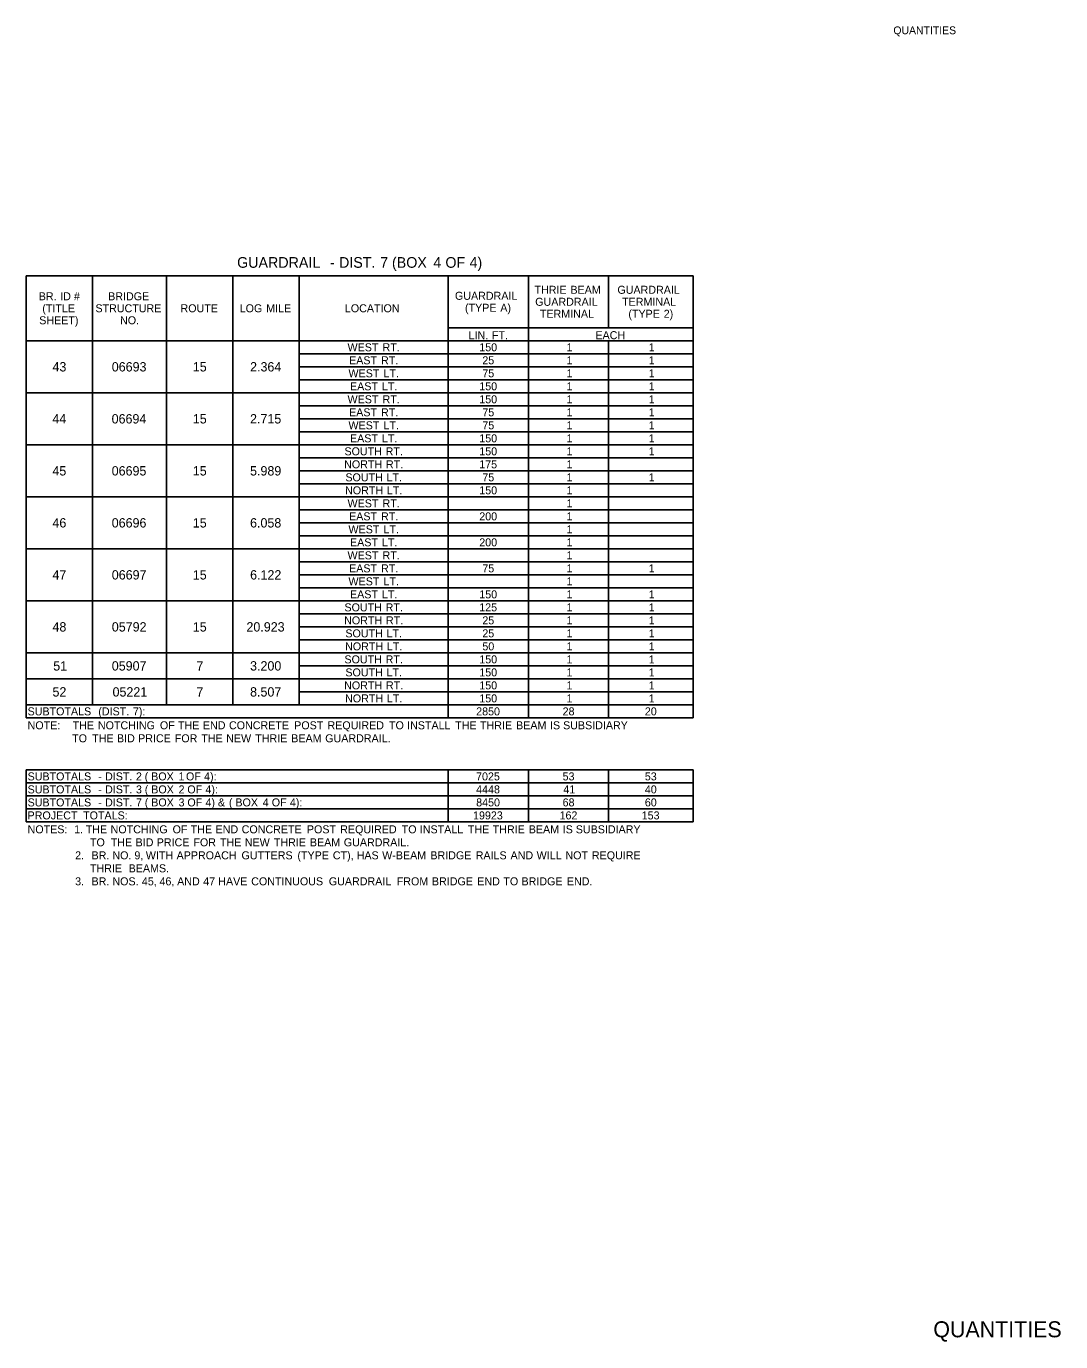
# Model space of a CAD drawing. Extents: x 544250 to 1930787, y -1948365 to 596640.
# Drawn here: x 550713 to 551489, y -1947044 to -1946058 of the extents above; entities that cross this region are included whole.
import ezdxf

# ---------------------------------------------------------------- set-up
doc = ezdxf.new("R2010")
doc.units = 0
for name, color, linetype in [('Default', 7, 'Continuous'), ('R_Border', 7, 'Continuous'), ('R_Border Prem', 7, 'Continuous')]:
    doc.layers.add(name, color=color, linetype=linetype)

msp = doc.modelspace()

# ---------------------------------------------------------------- linework, layer by layer
at = {"layer": 'Default'}
for p, q in [((550712.7, -1946245.01), (551212.87, -1946245.01)), ((550712.7, -1946245.01), (551212.87, -1946245.01)), ((550712.7, -1946576.51), (550712.7, -1946245.01)), ((550712.7, -1946576.51), (550712.7, -1946245.01)), ((550762.42, -1946566.76), (550762.42, -1946245.01)), ((550818, -1946566.76), (550818, -1946245.01)), ((550867.72, -1946566.76), (550867.72, -1946245.01)), ((550917.45, -1946566.76), (550917.45, -1946245.01)), ((551029.09, -1946576.51), (551029.09, -1946245.01)), ((551089.54, -1946576.51), (551089.54, -1946245.01)), ((551149.5, -1946284.01), (551149.5, -1946245.01)), ((551212.87, -1946576.51), (551212.87, -1946245.01)), ((551212.87, -1946293.76), (551212.87, -1946245.01)), ((551029.09, -1946284.01), (551212.87, -1946284.01)), ((551089.54, -1946293.76), (551089.54, -1946284.01)), ((550712.7, -1946293.76), (551212.87, -1946293.76)), ((551149.5, -1946576.51), (551149.5, -1946293.76)), ((550917.45, -1946303.51), (551212.87, -1946303.51)), ((550917.45, -1946313.26), (551212.87, -1946313.26)), ((550917.45, -1946323.01), (551212.87, -1946323.01)), ((550712.7, -1946332.76), (551212.87, -1946332.76)), ((550917.45, -1946342.51), (551212.87, -1946342.51)), ((550917.45, -1946352.26), (551212.87, -1946352.26)), ((550917.45, -1946362.01), (551212.87, -1946362.01)), ((550712.7, -1946371.76), (551212.87, -1946371.76)), ((550917.45, -1946381.51), (551212.87, -1946381.51)), ((550917.45, -1946391.26), (551212.87, -1946391.26)), ((550917.45, -1946401.01), (551212.87, -1946401.01)), ((550712.7, -1946410.76), (551212.87, -1946410.76)), ((550917.45, -1946420.51), (551212.87, -1946420.51)), ((550917.45, -1946430.26), (551212.87, -1946430.26)), ((550917.45, -1946440.01), (551212.87, -1946440.01)), ((550712.7, -1946449.76), (551212.87, -1946449.76)), ((550917.45, -1946459.51), (551212.87, -1946459.51)), ((550917.45, -1946469.26), (551212.87, -1946469.26)), ((550917.45, -1946479.01), (551212.87, -1946479.01)), ((550712.7, -1946488.76), (551212.87, -1946488.76)), ((551212.87, -1946576.51), (551212.87, -1946488.76)), ((550917.45, -1946498.51), (551212.87, -1946498.51)), ((550917.45, -1946508.26), (551212.87, -1946508.26)), ((550917.45, -1946518.01), (551212.87, -1946518.01)), ((550712.7, -1946527.76), (551212.87, -1946527.76)), ((550917.45, -1946537.51), (551212.87, -1946537.51)), ((550712.7, -1946547.26), (550917.45, -1946547.26)), ((550762.42, -1946547.26), (550917.45, -1946547.26)), ((550917.45, -1946547.26), (551212.87, -1946547.26)), ((550917.45, -1946547.26), (551212.87, -1946547.26)), ((550917.45, -1946557.01), (551212.87, -1946557.01)), ((550712.7, -1946566.76), (551212.87, -1946566.76)), ((550762.42, -1946566.76), (550917.45, -1946566.76)), ((550917.45, -1946566.76), (551212.87, -1946566.76)), ((551089.54, -1946576.51), (551089.54, -1946566.76)), ((551149.5, -1946576.51), (551149.5, -1946566.76)), ((550712.7, -1946576.51), (551212.87, -1946576.51)), ((550712.7, -1946615.51), (551212.87, -1946615.51)), ((550712.7, -1946654.51), (550712.7, -1946615.51)), ((550712.7, -1946654.51), (550712.7, -1946615.51)), ((551029.09, -1946654.51), (551029.09, -1946615.51)), ((551089.54, -1946654.51), (551089.54, -1946615.51)), ((551149.5, -1946654.51), (551149.5, -1946615.51)), ((551212.87, -1946654.51), (551212.87, -1946615.51)), ((551212.87, -1946654.51), (551212.87, -1946615.51)), ((550712.7, -1946625.26), (551212.87, -1946625.26)), ((550712.7, -1946635.01), (551212.87, -1946635.01)), ((550712.7, -1946644.76), (551212.87, -1946644.76)), ((550712.7, -1946654.51), (551212.87, -1946654.51))]:
    msp.add_line(p, q, dxfattribs=at)

# ---------------------------------------------------------------- texts
for s, height, p in [('GUARDRAIL', 8, (550870.85, -1946239.01)), (' DIST.', 8, (550944.33, -1946239.01)), (' 7', 8, (550975.23, -1946239.01)), (' (BOX', 8, (550984.06, -1946239.01)), (' 4', 8, (551015.09, -1946239.01)), (' OF', 8, (551024.15, -1946239.01)), (' 4)', 8, (551042.26, -1946239.01)), (' -', 8, (550937.59, -1946239.01)), ('THRIE', 6, (551093.94, -1946258.51)), (' BEAM', 6, (551118.68, -1946258.51)), ('GUARDRAIL', 6, (551156.16, -1946258.51)), ('BR.', 6, (550722.04, -1946263.38)), (' ID', 6, (550735.9, -1946263.38)), (' #', 6, (550746.19, -1946263.38)), ('BRIDGE', 6, (550774.12, -1946263.38)), ('GUARDRAIL', 6, (551034.29, -1946263.01)), ('GUARDRAIL', 6, (551094.49, -1946267.51)), ('TERMINAL', 6, (551159.66, -1946267.51)), ('(TITLE', 6, (550724.73, -1946272.38)), ('STRUCTURE', 6, (550764.57, -1946272.38)), ('ROUTE', 6, (550828.4, -1946272.38)), ('LOG', 6, (550872.79, -1946272.38)), (' MILE', 6, (550890.45, -1946272.38)), ('LOCATION', 6, (550951.71, -1946272.38)), ('(TYPE', 6, (551041.81, -1946272.01)), (' A)', 6, (551066.08, -1946272.01)), ('TERMINAL', 6, (551097.99, -1946276.51)), ('(TYPE', 6, (551164.38, -1946276.51)), (' 2)', 6, (551188.65, -1946276.51)), ('SHEET)', 6, (550722.41, -1946281.38)), ('NO.', 6, (550783.05, -1946281.38)), ('LIN.', 6, (551044.52, -1946292.56)), (' FT.', 6, (551059.78, -1946292.56)), ('EACH', 6, (551139.65, -1946292.56)), ('WEST', 6, (550953.69, -1946301.63)), (' RT.', 6, (550977.74, -1946301.63)), ('150', 6, (551052.52, -1946301.63)), ('1', 6, (551117.96, -1946301.63)), ('1', 6, (551179.63, -1946301.63)), ('43', 7, (550732.34, -1946316.76)), ('06693', 7, (550776.83, -1946316.76)), ('15', 7, (550837.62, -1946316.76)), ('2.364', 7, (550880.59, -1946316.76)), ('EAST', 6, (550954.85, -1946311.38)), (' RT.', 6, (550976.58, -1946311.38)), ('25', 6, (551054.82, -1946311.38)), ('1', 6, (551117.96, -1946311.38)), ('1', 6, (551179.63, -1946311.38)), ('WEST', 6, (550954.39, -1946321.13)), (' LT.', 6, (550978.44, -1946321.13)), ('75', 6, (551054.82, -1946321.13)), ('1', 6, (551117.96, -1946321.13)), ('1', 6, (551179.63, -1946321.13)), ('EAST', 6, (550955.55, -1946330.88)), (' LT.', 6, (550977.28, -1946330.88)), ('150', 6, (551052.52, -1946330.88)), ('1', 6, (551117.96, -1946330.88)), ('1', 6, (551179.63, -1946330.88)), ('WEST', 6, (550953.69, -1946340.63)), (' RT.', 6, (550977.74, -1946340.63)), ('150', 6, (551052.52, -1946340.63)), ('1', 6, (551117.96, -1946340.63)), ('1', 6, (551179.63, -1946340.63)), ('44', 7, (550732.24, -1946355.76)), ('06694', 7, (550776.73, -1946355.76)), ('15', 7, (550837.62, -1946355.76)), ('2.715', 7, (550880.55, -1946355.76)), ('EAST', 6, (550954.85, -1946350.38)), (' RT.', 6, (550976.58, -1946350.38)), ('75', 6, (551054.82, -1946350.38)), ('1', 6, (551117.96, -1946350.38)), ('1', 6, (551179.63, -1946350.38)), ('WEST', 6, (550954.39, -1946360.13)), (' LT.', 6, (550978.44, -1946360.13)), ('75', 6, (551054.82, -1946360.13)), ('1', 6, (551117.96, -1946360.13)), ('1', 6, (551179.63, -1946360.13)), ('EAST', 6, (550955.55, -1946369.88)), (' LT.', 6, (550977.28, -1946369.88)), ('150', 6, (551052.52, -1946369.88)), ('1', 6, (551117.96, -1946369.88)), ('1', 6, (551179.63, -1946369.88)), ('SOUTH', 6, (550951.38, -1946379.63)), (' RT.', 6, (550980.05, -1946379.63)), ('150', 6, (551052.52, -1946379.63)), ('1', 6, (551117.96, -1946379.63)), ('1', 6, (551179.63, -1946379.63)), ('45', 7, (550732.27, -1946394.76)), ('06695', 7, (550776.77, -1946394.76)), ('15', 7, (550837.62, -1946394.76)), ('5.989', 7, (550880.57, -1946394.76)), ('NORTH', 6, (550951.15, -1946389.38)), (' RT.', 6, (550980.28, -1946389.38)), ('175', 6, (551052.49, -1946389.38)), ('1', 6, (551117.96, -1946389.38)), ('SOUTH', 6, (550952.08, -1946399.13)), (' LT.', 6, (550980.75, -1946399.13)), ('75', 6, (551054.82, -1946399.13)), ('1', 6, (551117.96, -1946399.13)), ('1', 6, (551179.63, -1946399.13)), ('NORTH', 6, (550951.85, -1946408.88)), (' LT.', 6, (550980.98, -1946408.88)), ('150', 6, (551052.52, -1946408.88)), ('1', 6, (551117.96, -1946408.88)), ('WEST', 6, (550953.69, -1946418.63)), ('EAST', 6, (550954.85, -1946428.38)), (' RT.', 6, (550976.58, -1946428.38)), (' RT.', 6, (550977.74, -1946418.63)), ('200', 6, (551052.52, -1946428.38)), ('1', 6, (551117.96, -1946418.63)), ('1', 6, (551117.96, -1946428.38)), ('46', 7, (550732.3, -1946433.76)), ('06696', 7, (550776.79, -1946433.76)), ('15', 7, (550837.62, -1946433.76)), ('6.058', 7, (550880.57, -1946433.76)), ('WEST', 6, (550954.39, -1946438.13)), (' LT.', 6, (550978.44, -1946438.13)), ('1', 6, (551117.96, -1946438.13)), ('EAST', 6, (550955.55, -1946447.88)), (' LT.', 6, (550977.28, -1946447.88)), ('200', 6, (551052.52, -1946447.88)), ('1', 6, (551117.96, -1946447.88)), ('WEST', 6, (550953.69, -1946457.63)), (' RT.', 6, (550977.74, -1946457.63)), ('1', 6, (551117.96, -1946457.63)), ('EAST', 6, (550954.85, -1946467.38)), (' RT.', 6, (550976.58, -1946467.38)), ('75', 6, (551054.82, -1946467.38)), ('1', 6, (551117.96, -1946467.38)), ('1', 6, (551179.63, -1946467.38)), ('47', 7, (550732.34, -1946472.76)), ('06697', 7, (550776.84, -1946472.76)), ('15', 7, (550837.62, -1946472.76)), ('6.122', 7, (550880.61, -1946472.76)), ('WEST', 6, (550954.39, -1946477.13)), (' LT.', 6, (550978.44, -1946477.13)), ('1', 6, (551117.96, -1946477.13)), ('EAST', 6, (550955.55, -1946486.88)), (' LT.', 6, (550977.28, -1946486.88)), ('150', 6, (551052.52, -1946486.88)), ('1', 6, (551117.96, -1946486.88)), ('1', 6, (551179.63, -1946486.88)), ('SOUTH', 6, (550951.38, -1946496.63)), (' RT.', 6, (550980.05, -1946496.63)), ('125', 6, (551052.49, -1946496.63)), ('1', 6, (551117.96, -1946496.63)), ('1', 6, (551179.63, -1946496.63)), ('NORTH', 6, (550951.15, -1946506.38)), (' RT.', 6, (550980.28, -1946506.38)), ('25', 6, (551054.82, -1946506.38)), ('1', 6, (551117.96, -1946506.38)), ('1', 6, (551179.63, -1946506.38)), ('48', 7, (550732.34, -1946511.76)), ('05792', 7, (550776.87, -1946511.76)), ('15', 7, (550837.62, -1946511.76)), ('20.923', 7, (550877.86, -1946511.76)), ('SOUTH', 6, (550952.08, -1946516.13)), (' LT.', 6, (550980.75, -1946516.13)), ('25', 6, (551054.82, -1946516.13)), ('1', 6, (551117.96, -1946516.13)), ('1', 6, (551179.63, -1946516.13)), ('NORTH', 6, (550951.85, -1946525.88)), (' LT.', 6, (550980.98, -1946525.88)), ('50', 6, (551054.85, -1946525.88)), ('1', 6, (551117.96, -1946525.88)), ('1', 6, (551179.63, -1946525.88)), ('SOUTH', 6, (550951.38, -1946535.63)), (' RT.', 6, (550980.05, -1946535.63)), ('150', 6, (551052.52, -1946535.63)), ('1', 6, (551117.96, -1946535.63)), ('1', 6, (551179.63, -1946535.63)), ('51', 7, (550732.92, -1946541.01)), ('05907', 7, (550776.84, -1946541.01)), ('7', 7, (550840.36, -1946541.01)), ('3.200', 7, (550880.59, -1946541.01)), ('SOUTH', 6, (550952.08, -1946545.38)), (' LT.', 6, (550980.75, -1946545.38)), ('150', 6, (551052.52, -1946545.38)), ('1', 6, (551117.96, -1946545.38)), ('1', 6, (551179.63, -1946545.38)), ('NORTH', 6, (550951.15, -1946555.13)), (' RT.', 6, (550980.28, -1946555.13)), ('150', 6, (551052.52, -1946555.13)), ('1', 6, (551117.96, -1946555.13)), ('1', 6, (551179.63, -1946555.13)), ('52', 7, (550732.37, -1946560.51)), ('05221', 7, (550777.41, -1946560.51)), ('7', 7, (550840.36, -1946560.51)), ('8.507', 7, (550880.58, -1946560.51)), ('NORTH', 6, (550951.85, -1946564.88)), (' LT.', 6, (550980.98, -1946564.88)), ('150', 6, (551052.52, -1946564.88)), ('1', 6, (551117.96, -1946564.88)), ('1', 6, (551179.63, -1946564.88)), ('SUBTOTALS', 6, (550713.67, -1946574.63)), (' (DIST.', 6, (550764.5, -1946574.63)), (' 7):', 6, (550790.47, -1946574.63)), ('2850', 6, (551050.2, -1946574.63)), ('28', 6, (551115.05, -1946574.63)), ('20', 6, (551176.73, -1946574.63)), ('NOTE:', 6, (550713.67, -1946585.06)), ('    THE', 6, (550738.56, -1946585.06)), (' NOTCHING', 6, (550764.19, -1946585.06)), (' OF', 6, (550810.71, -1946585.06)), (' THE', 6, (550824.29, -1946585.06)), (' END', 6, (550842.94, -1946585.06)), (' CONCRETE', 6, (550862.53, -1946585.06)), (' POST', 6, (550911.45, -1946585.06)), (' REQUIRED', 6, (550936.44, -1946585.06)), (' TO', 6, (550982.58, -1946585.06)), (' INSTALL', 6, (550996.17, -1946585.06)), (' THE', 6, (551032.21, -1946585.06)), (' THRIE', 6, (551050.86, -1946585.06)), (' BEAM', 6, (551077.9, -1946585.06)), (' IS', 6, (551103.35, -1946585.06)), (' SUBSIDIARY', 6, (551113.16, -1946585.06)), ('               TO', 6, (550713.67, -1946594.81)), (' THE', 6, (550759.86, -1946594.81)), (' BID', 6, (550778.51, -1946594.81)), (' PRICE', 6, (550794.36, -1946594.81)), (' FOR', 6, (550821.87, -1946594.81)), (' THE', 6, (550841.78, -1946594.81)), (' NEW', 6, (550860.43, -1946594.81)), (' THRIE', 6, (550882.22, -1946594.81)), (' BEAM', 6, (550909.25, -1946594.81)), (' GUARDRAIL.', 6, (550934.71, -1946594.81)), ('SUBTOTALS', 6, (550713.67, -1946623.38)), (' DIST.', 6, (550769.56, -1946623.38)), (' 2', 6, (550792.74, -1946623.38)), (' (', 6, (550799.3, -1946623.38)), (' BOX', 6, (550804.15, -1946623.38)), (' 1', 6, (550824.64, -1946623.38)), (' OF', 6, (550830.27, -1946623.38)), (' 4):', 6, (550843.85, -1946623.38)), ('7025', 6, (551050.12, -1946623.38)), ('53', 6, (551115.04, -1946623.38)), ('53', 6, (551176.71, -1946623.38)), ('SUBTOTALS', 6, (550713.67, -1946633.13)), (' -', 6, (550764.5, -1946623.38)), (' DIST.', 6, (550769.56, -1946633.13)), (' 3', 6, (550792.74, -1946633.13)), (' (', 6, (550799.36, -1946633.13)), (' BOX', 6, (550804.21, -1946633.13)), (' 2', 6, (550824.7, -1946633.13)), (' OF', 6, (550831.27, -1946633.13)), (' 4):', 6, (550844.85, -1946633.13)), ('4448', 6, (551050.18, -1946633.13)), ('41', 6, (551115.54, -1946633.13)), ('40', 6, (551176.73, -1946633.13)), ('SUBTOTALS', 6, (550713.67, -1946642.88)), (' -', 6, (550764.5, -1946633.13)), (' DIST.', 6, (550769.56, -1946642.88)), (' 7', 6, (550792.74, -1946642.88)), (' (', 6, (550799.35, -1946642.88)), (' BOX', 6, (550804.2, -1946642.88)), (' 3', 6, (550824.69, -1946642.88)), (' OF', 6, (550831.32, -1946642.88)), (' 4)', 6, (550844.9, -1946642.88)), (' &', 6, (550854.24, -1946642.88)), (' (', 6, (550862.49, -1946642.88)), (' BOX', 6, (550867.34, -1946642.88)), (' 4', 6, (550887.83, -1946642.88)), (' OF', 6, (550894.63, -1946642.88)), (' 4):', 6, (550908.21, -1946642.88)), ('8450', 6, (551050.2, -1946642.88)), ('68', 6, (551115.05, -1946642.88)), ('60', 6, (551176.73, -1946642.88)), ('PROJECT', 6, (550713.67, -1946652.63)), (' TOTALS:', 6, (550753.1, -1946652.63)), (' -', 6, (550764.5, -1946642.88)), ('19923', 6, (551047.84, -1946652.63)), ('162', 6, (551112.74, -1946652.63)), ('153', 6, (551174.38, -1946652.63)), ('NOTES:', 6, (550713.67, -1946663.06)), ('  1.', 6, (550744.15, -1946663.06)), (' THE', 6, (550755.07, -1946663.06)), (' NOTCHING', 6, (550773.72, -1946663.06)), (' OF', 6, (550820.23, -1946663.06)), (' THE', 6, (550833.82, -1946663.06)), (' END', 6, (550852.47, -1946663.06)), (' CONCRETE', 6, (550872.05, -1946663.06)), (' POST', 6, (550920.98, -1946663.06)), (' REQUIRED', 6, (550945.96, -1946663.06)), (' TO', 6, (550992.1, -1946663.06)), (' INSTALL', 6, (551005.69, -1946663.06)), (' THE', 6, (551041.74, -1946663.06)), (' THRIE', 6, (551060.38, -1946663.06)), (' BEAM', 6, (551087.42, -1946663.06)), (' IS', 6, (551112.88, -1946663.06)), (' SUBSIDIARY', 6, (551122.69, -1946663.06)), ('                     TO', 6, (550713.67, -1946672.81)), (' THE', 6, (550773.83, -1946672.81)), (' BID', 6, (550792.47, -1946672.81)), (' PRICE', 6, (550808.33, -1946672.81)), (' FOR', 6, (550835.83, -1946672.81)), (' THE', 6, (550855.74, -1946672.81)), (' NEW', 6, (550874.39, -1946672.81)), (' THRIE', 6, (550896.19, -1946672.81)), (' BEAM', 6, (550923.22, -1946672.81)), (' GUARDRAIL.', 6, (550948.68, -1946672.81)), ('                2.', 6, (550713.67, -1946682.56)), ('  BR.', 6, (550757.17, -1946682.56)), (' NO.', 6, (550775.07, -1946682.56)), (' 9,', 6, (550791.57, -1946682.56)), (' WITH', 6, (550800.14, -1946682.56)), (' APPROACH', 6, (550823.21, -1946682.56)), (' GUTTERS', 6, (550871.92, -1946682.56)), (' (TYPE', 6, (550913.87, -1946682.56)), (' CT),', 6, (550940.44, -1946682.56)), (' HAS', 6, (550958.32, -1946682.56)), (' W-BEAM', 6, (550977.45, -1946682.56)), (' BRIDGE', 6, (551013.61, -1946682.56)), (' RAILS', 6, (551047.63, -1946682.56)), (' AND', 6, (551073.75, -1946682.56)), (' WILL', 6, (551093.33, -1946682.56)), (' NOT', 6, (551114.92, -1946682.56)), (' REQUIRE', 6, (551134.78, -1946682.56)), ('                     THRIE', 6, (550713.67, -1946692.31)), (' BEAMS.', 6, (550787.26, -1946692.31)), ('                3.', 6, (550713.67, -1946702.06)), ('  BR.', 6, (550757.17, -1946702.06)), (' NOS.', 6, (550775.07, -1946702.06)), (' 45,', 6, (550797.17, -1946702.06)), (' 46,', 6, (550810.4, -1946702.06)), (' AND', 6, (550823.63, -1946702.06)), (' 47', 6, (550843.21, -1946702.06)), (' HAVE', 6, (550854.48, -1946702.06)), (' CONTINUOUS', 6, (550879.19, -1946702.06)), (' GUARDRAIL', 6, (550937.44, -1946702.06)), (' FROM', 6, (550988.38, -1946702.06)), (' BRIDGE', 6, (551014.76, -1946702.06)), (' END', 6, (551048.79, -1946702.06)), (' TO', 6, (551068.37, -1946702.06)), (' BRIDGE', 6, (551081.97, -1946702.06)), (' END.', 6, (551115.99, -1946702.06))]:
    msp.add_text(s, height=height, dxfattribs=at).set_placement(p)
at = {"layer": 'R_Border'}
msp.add_text('QUANTITIES', height=12, rotation=360, dxfattribs=at).set_placement((551393.15, -1947040.95))
at = {"layer": 'R_Border Prem'}
msp.add_text('QUANTITIES', height=5.862, rotation=360, dxfattribs=at).set_placement((551363.17, -1946063.9))

doc.saveas('drawing.dxf')
